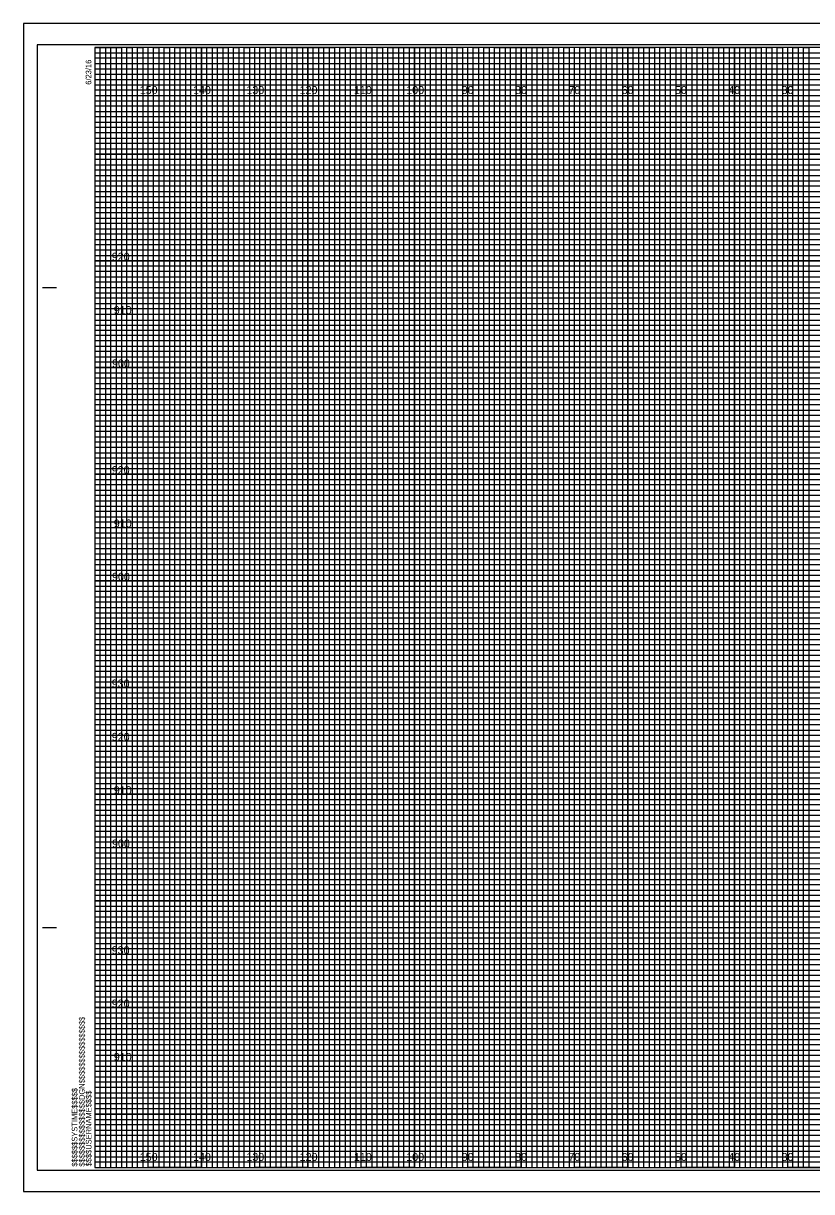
# Model space of a CAD drawing. Extents: x -13 to 323, y -4 to 214.
# Drawn here: x -13.4 to 134.5, y -4.5 to 214.5 of the extents above; entities that cross this region are included whole.
import ezdxf

# ---------------------------------------------------------------- set-up
doc = ezdxf.new("R2010")
doc.units = 0
for name, color, linetype in [('Prop XS Elevation Labels', 7, 'Continuous'), ('Prop XS Offset Labels', 7, 'Continuous'), ('Sheet Cross Section CELL', 7, 'Continuous'), ('Sheet Cross Section Grid Major CELL', 7, 'Continuous'), ('Sheet Cross Section Grid Middle CELL', 7, 'Continuous'), ('Sheet Cross Section Grid Minor 1 CELL', 7, 'Continuous'), ('Sheet Cross Section Grid Minor 2 CELL', 7, 'Continuous'), ('Sheet Cutting Line CELL', 7, 'Continuous'), ('Sheet DOT Grid CELL', 7, 'Continuous'), ('Sheet Plot Border Inside CELL', 7, 'Continuous'), ('Sheet Plot Border Outside CELL', 7, 'Continuous')]:
    doc.layers.add(name, color=color, linetype=linetype)

msp = doc.modelspace()

# ---------------------------------------------------------------- linework, layer by layer
at = {"layer": 'Sheet Cross Section CELL'}
for p, q in [((-9.8, 165), (-7.3, 165)), ((-9.7, 165), (-7.2, 165)), ((-9.8, 45), (-7.3, 45)), ((-9.7, 45), (-7.2, 45)), ((0, 0), (0, 0)), ((0, 0), (0, 0)), ((0, 0), (0, 0)), ((0, 0), (0, 0)), ((0, 0), (0, 0)), ((0, 0), (0, 0)), ((0, 0), (0, 0))]:
    msp.add_line(p, q, dxfattribs=at)
msp.add_lwpolyline([(320, 210), (0, 210), (0, 0), (320, 0)], close=True, dxfattribs=at)
at = {"layer": 'Sheet Cross Section Grid Major CELL'}
for p, q in [((10, 210), (0, 210)), ((10, 0), (10, 210)), ((30, 210), (20, 210)), ((20, 210), (20, 0)), ((30, 0), (30, 210)), ((50, 210), (40, 210)), ((40, 210), (40, 0)), ((50, 0), (50, 210)), ((70, 210), (60, 210)), ((60, 210), (60, 0)), ((70, 0), (70, 210)), ((90, 210), (80, 210)), ((80, 210), (80, 0)), ((90, 0), (90, 210)), ((110, 210), (100, 210)), ((100, 210), (100, 0)), ((110, 0), (110, 210)), ((130, 210), (120, 210)), ((120, 210), (120, 0)), ((130, 0), (130, 210)), ((20, 0), (10, 0)), ((40, 0), (30, 0)), ((60, 0), (50, 0)), ((80, 0), (70, 0)), ((100, 0), (90, 0)), ((120, 0), (110, 0)), ((140, 0), (130, 0))]:
    msp.add_line(p, q, dxfattribs=at)
for points in [[(0, 200), (320, 200), (320, 190), (0, 190)], [(0, 180), (320, 180), (320, 170), (0, 170)], [(0, 160), (320, 160), (320, 150), (0, 150)], [(0, 140), (320, 140), (320, 130), (0, 130)], [(0, 120), (320, 120), (320, 110), (0, 110)], [(0, 100), (320, 100), (320, 90), (0, 90)], [(0, 80), (320, 80), (320, 70), (0, 70)], [(0, 60), (320, 60), (320, 50), (0, 50)], [(0, 40), (320, 40), (320, 30), (0, 30)], [(0, 20), (320, 20), (320, 10), (0, 10)]]:
    msp.add_lwpolyline(points, dxfattribs=at)
at = {"layer": 'Sheet Cross Section Grid Middle CELL'}
for points in [[(0, 210), (5, 210), (5, 0), (15, 0), (15, 210), (25, 210), (25, 0), (35, 0), (35, 210), (45, 210), (45, 0), (55, 0), (55, 210), (65, 210), (65, 0), (75, 0), (75, 210), (85, 210), (85, 0), (95, 0), (95, 210), (105, 210), (105, 0), (115, 0), (115, 210), (125, 210), (125, 0), (135, 0)], [(0, 205), (275, 205)], [(0, 185), (320, 185), (320, 195), (0, 195)], [(0, 165), (320, 165), (320, 175), (0, 175)], [(0, 145), (320, 145), (320, 155), (0, 155)], [(0, 125), (320, 125), (320, 135), (0, 135)], [(0, 105), (320, 105), (320, 115), (0, 115)], [(0, 85), (320, 85), (320, 95), (0, 95)], [(0, 65), (320, 65), (320, 75), (0, 75)], [(0, 45), (320, 45), (320, 55), (0, 55)], [(0, 25), (320, 25), (320, 35), (0, 35)], [(0, 5), (320, 5), (320, 15), (0, 15)]]:
    msp.add_lwpolyline(points, dxfattribs=at)
at = {"layer": 'Sheet Cross Section Grid Minor 1 CELL'}
for p, q in [((0, 209), (260, 209)), ((260, 207.98), (0, 207.98)), ((0, 207.98), (0, 207)), ((0, 207), (260, 207)), ((260, 205.89), (0, 205.89)), ((0, 205.89), (0, 204)), ((0, 204), (320, 204))]:
    msp.add_line(p, q, dxfattribs=at)
for points in [[(0, 203), (270, 203), (320, 203), (320, 202), (0, 202)], [(0, 201), (320, 201), (320, 199), (0, 199)], [(0, 198), (320, 198), (320, 197), (0, 196.98)], [(0, 196), (320, 196), (320, 194), (0, 194)], [(0, 193), (320, 193), (320, 192), (0, 192)], [(0, 191), (320, 191), (320, 189), (0, 189)], [(0, 188), (320, 188), (320, 187), (0, 187)], [(0, 186), (320, 186), (320, 184), (0, 184)], [(0, 183), (320, 183), (320, 182), (0, 182)], [(0, 181), (320, 181), (320, 179), (0, 179)], [(0, 178), (320, 178), (320, 177), (0, 177)], [(0, 176), (320, 176), (320, 173.95), (320, 173), (320, 172), (0, 172)], [(0, 174), (320, 174), (320, 173), (0, 173)], [(0, 171), (320, 171), (320, 169), (0, 169.03)], [(0, 169.03), (320, 169), (320, 168), (0, 168)], [(0, 167), (320, 167), (320, 166), (0, 166)], [(0, 164), (320, 164), (320, 163), (0, 163)], [(0, 162), (320, 162), (320, 161), (0, 161)], [(-0.07, 158.89), (320, 158.89), (320, 157.88), (-0.07, 157.88)], [(0, 157), (320, 157), (320, 156), (0, 156)], [(0, 154), (320, 154), (320, 153), (0, 153)], [(0, 152), (320, 152), (320, 151), (0, 151)], [(0, 149), (320, 149), (320, 148), (0, 148)], [(0, 147), (320, 147), (320, 146), (0, 146)], [(0, 144), (320, 144), (320, 143), (0, 143)], [(0, 142), (320, 142), (320, 141), (0, 141)], [(0, 139), (320, 139), (319.99, 137.98), (0, 138)], [(0, 137), (320, 137), (320, 136), (0, 136)], [(0, 134), (320, 134), (320, 133), (0, 133)], [(0, 132), (320, 132), (320, 131), (0, 131)], [(0, 129), (320, 129), (320, 128), (0, 128)], [(0, 127), (320, 127), (320, 126), (0, 126)], [(0, 124), (320, 124), (320, 123), (0, 123)], [(0, 122), (320, 122), (320, 121), (0, 121)], [(0, 119), (320, 119), (320, 118), (0, 118)], [(0, 116.99), (320.07, 116.91), (320, 116), (0, 116)], [(0, 114), (320, 114), (320, 113), (0, 113)], [(0, 112), (320, 112), (320, 111), (0, 111)], [(0, 109), (320, 109), (320, 108), (0, 108)], [(0, 107), (320, 107), (320, 106), (0, 106)], [(0, 104), (320, 104), (320, 103), (0, 103)], [(0, 102), (320, 102), (320, 101), (0, 101)], [(0, 99), (320, 99), (320, 98), (0, 98)], [(0, 97), (320, 97), (320, 96), (0, 96)], [(0, 94), (320, 94), (320, 93), (0, 93)], [(0, 92), (320, 92), (320, 91), (0, 91)], [(0, 89), (320, 89), (320, 88), (0, 88)], [(0, 87), (320, 87), (320, 86), (0, 86)], [(0, 84), (320, 84), (320, 83), (0, 83)], [(0, 82), (320, 82), (320, 81), (0, 81)], [(0, 79), (320, 79), (319.99, 77.98), (0, 78)], [(0, 77), (320, 77), (320, 76), (0, 76)], [(0, 74), (320, 74), (320, 73), (0, 73)], [(0, 72), (320, 72), (320, 71), (0, 71)], [(0, 69), (320, 69), (320, 68), (0, 68)], [(0, 67), (320, 67), (320, 66), (0, 66)], [(0, 64), (320, 64), (320, 63), (0, 63)], [(0, 62), (320, 62), (320, 61), (0, 61)], [(0, 59), (320, 59), (320, 58), (0, 58)], [(0, 56.99), (320.07, 56.91), (320, 56), (0, 56)], [(0, 54), (320, 54), (320, 53), (0, 53)], [(0, 52), (320, 52), (320, 51), (0, 51)], [(0, 49), (320, 49), (320, 48), (0, 48)], [(0, 47), (320, 47), (320, 46), (0, 46)], [(0, 44), (320, 44), (320, 43), (0, 43)], [(0, 42), (320, 42), (320, 41), (0, 41)], [(0, 39), (320, 39), (320, 38), (0, 38)], [(0, 37), (320, 37), (320, 36), (0, 36)], [(0, 34), (320, 34), (320, 33), (0, 33)], [(0, 32), (320, 32), (320, 31), (0, 31)], [(0, 29), (320, 29), (320, 28), (0, 28)], [(0, 27), (320, 27), (320, 26), (0, 26)], [(0, 24), (320, 24), (320, 23), (0, 23)], [(0, 22), (320, 22), (320, 21), (0, 21)], [(0, 19), (320, 19), (320, 18), (0, 18)], [(0, 17), (320, 17), (320, 16), (0, 16)], [(0, 14), (320, 14), (320, 13), (0, 13)], [(0, 12), (320, 12), (320, 11), (0, 11)], [(0, 9), (320, 9), (320, 8), (0, 8)], [(0, 7), (320, 7), (320, 6), (0, 6)], [(0, 4), (320, 4), (320, 3), (0, 3)], [(0, 2), (320, 2), (320, 1), (0, 1)]]:
    msp.add_lwpolyline(points, dxfattribs=at)
at = {"layer": 'Sheet Cross Section Grid Minor 2 CELL'}
for points in [[(0, 0), (1, 0), (1, 210), (2, 210), (2, 0)], [(2, 0), (3, 0), (3, 210), (4, 210), (4, 0)], [(5, 0), (6, 0), (6, 210), (7, 210), (7, 0)], [(7, 0), (8, 0), (8, 210), (9, 210), (9, 0)], [(10, 0), (11, 0), (11, 210), (12, 210), (12, 0)], [(12, 0), (13, 0), (13, 210), (14, 210), (14, 0)], [(15, 0), (16, 0), (16, 210), (17, 210), (17, 0)], [(17, 0), (18, 0), (18, 210), (19, 210), (19, 0)], [(20, 0), (21, 0), (21, 210), (22, 210), (22, 0)], [(22, 0), (23, 0), (23, 210), (24, 210), (24, 0)], [(25, 0), (26, 0), (26, 210), (27, 210), (27, 0)], [(27, 0), (28, 0), (28, 210), (29, 210), (29, 0)], [(30, 0), (31, 0), (31, 210), (32, 210), (32, 0)], [(32, 0), (33, 0), (33, 210), (34, 210), (34, 0)], [(35, 0), (36, 0), (36, 210), (37, 210), (37, 0)], [(37, 0), (38, 0), (38, 210), (39, 210), (39, 0)], [(40, 0), (41, 0), (41, 210), (42, 210), (42, 0)], [(42, 0), (43, 0), (43, 210), (44, 210), (44, 0)], [(45, 0), (46, 0), (46, 210), (47, 210), (47, 0)], [(47, 0), (48, 0), (48, 210), (49, 210), (49, 0)], [(50, 0), (51, 0), (51, 210), (52, 210), (52, 0)], [(52, 0), (53, 0), (53, 210), (54, 210), (54, 0)], [(55, 0), (56, 0), (56, 210), (57, 210), (57, 0)], [(57, 0), (58, 0), (58, 210), (59, 210), (59, 0)], [(60, 0), (61, 0), (61, 210), (62, 210), (62, 0)], [(62, 0), (63, 0), (63, 210), (64, 210), (64, 0)], [(65, 0), (66, 0), (66, 210), (67, 210), (67, 0)], [(67, 0), (68, 0), (68, 210), (69, 210), (69, 0)], [(70, 0), (71, 0), (71, 210), (72, 210), (72, 0)], [(72, 0), (73, 0), (73, 210), (74, 210), (74, 0)], [(75, 0), (76, 0), (76, 210), (77, 210), (77, 0)], [(77, 0), (78, 0), (78, 210), (79, 210), (79, 0)], [(80, 0), (81, 0), (81, 210), (82, 210), (82, 0)], [(82, 0), (83, 0), (83, 210), (84, 210), (84, 0)], [(85, 0), (86, 0), (86, 210), (87, 210), (87, 0)], [(87, 0), (88, 0), (88, 210), (89, 210), (89, 0)], [(90, 0), (91, 0), (91, 210), (92, 210), (92, 0)], [(92, 0), (93, 0), (93, 210), (94, 210), (94, 0)], [(95, 0), (96, 0), (96, 210), (97, 210), (97, 0)], [(97, 0), (98, 0), (98, 210), (99, 210), (99, 0)], [(100, 0), (101, 0), (101, 210), (102, 210), (102, 0)], [(102, 0), (103, 0), (103, 210), (104, 210), (104, 0)], [(105, 0), (106, 0), (106, 210), (107, 210), (107, 0)], [(107, 0), (108, 0), (108, 210), (109, 210), (109, 0)], [(110, 0), (111, 0), (111, 210), (112, 210), (112, 0)], [(112, 0), (113, 0), (113, 210), (114, 210), (114, 0)], [(115, 0), (116, 0), (116, 210), (117, 210), (117, 0)], [(117, 0), (118, 0), (118, 210), (119, 210), (119, 0)], [(120, 0), (121, 0), (121, 210), (122, 210), (122, 0)], [(122, 0), (123, 0), (123, 210), (124, 210), (124, 0)], [(125, 0), (126, 0), (126, 210), (127, 210), (127, 0)], [(127, 0), (128, 0), (128, 210), (129, 210), (129, 0)], [(130, 0), (131, 0), (131, 210), (132, 210), (132, 0)], [(132, 0), (133, 0), (133, 210), (134, 210), (134, 0)]]:
    msp.add_lwpolyline(points, dxfattribs=at)
at = {"layer": 'Sheet Cutting Line CELL'}
for p, q in [((323.3, 214.5), (-13.4, 214.5)), ((-13.4, 214.5), (-13.4, -4.5)), ((-13.4, -4.5), (323.3, -4.5))]:
    msp.add_line(p, q, dxfattribs=at)
at = {"layer": 'Sheet DOT Grid CELL'}
for p, q in [((10, 0), (10, 210)), ((20, 0), (20, 210)), ((30, 0), (30, 210)), ((40, 0), (40, 210)), ((50, 0), (50, 210)), ((60, 0), (60, 210)), ((70, 0), (70, 210)), ((80, 0), (80, 210)), ((90, 0), (90, 210)), ((100, 0), (100, 210)), ((110, 0), (110, 210)), ((120, 0), (120, 210)), ((130, 0), (130, 210)), ((0, 200), (320, 200)), ((0, 190), (320, 190)), ((0, 180), (320, 180)), ((0, 170), (320, 170)), ((0, 160), (320, 160)), ((0, 150), (320, 150)), ((0, 140), (320, 140)), ((0, 130), (320, 130)), ((0, 120), (320, 120)), ((0, 110), (320, 110)), ((0, 100), (320, 100)), ((0, 90), (320, 90)), ((0, 80), (320, 80)), ((0, 70), (320, 70)), ((0, 60), (320, 60)), ((0, 50), (320, 50)), ((0, 40), (320, 40)), ((0, 30), (320, 30)), ((0, 20), (320, 20)), ((0, 10), (320, 10))]:
    msp.add_line(p, q, dxfattribs=at)
at = {"layer": 'Sheet Plot Border Inside CELL'}
msp.add_lwpolyline([(-10.8, -0.5), (322.4, -0.5), (322.4, 210.5), (-10.8, 210.5)], close=True, dxfattribs=at)
at = {"layer": 'Sheet Plot Border Outside CELL'}
msp.add_lwpolyline([(-13.4, -4.5), (323.3, -4.5), (323.3, 214.5), (-13.4, 214.5)], close=True, dxfattribs=at)

# ---------------------------------------------------------------- texts
at = {"layer": 'Prop XS Elevation Labels'}
for s, p in [('920', (3.19, 170)), ('910', (3.57, 160)), ('900', (3.24, 150)), ('920', (3.19, 130)), ('910', (3.57, 120)), ('900', (3.24, 110)), ('930', (3.18, 90)), ('920', (3.19, 80)), ('910', (3.57, 70)), ('900', (3.24, 60)), ('930', (3.18, 40)), ('920', (3.19, 30)), ('910', (3.57, 20))]:
    msp.add_text(s, height=1.5, dxfattribs=at).set_placement(p)
at = {"layer": 'Prop XS Offset Labels'}
for s, p in [('150', (8.44, 201.25)), ('140', (18.44, 201.25)), ('130', (28.44, 201.25)), ('120', (38.44, 201.25)), ('110', (48.62, 201.25)), ('100', (58.44, 201.25)), ('90', (68.86, 201.25)), ('80', (78.86, 201.25)), ('70', (88.86, 201.25)), ('60', (98.86, 201.25)), ('50', (108.86, 201.25)), ('40', (118.86, 201.25)), ('30', (128.86, 201.25)), ('150', (8.44, 1.25)), ('140', (18.44, 1.25)), ('130', (28.44, 1.25)), ('120', (38.44, 1.25)), ('110', (48.62, 1.25)), ('100', (58.44, 1.25)), ('90', (68.86, 1.25)), ('80', (78.86, 1.25)), ('70', (88.86, 1.25)), ('60', (98.86, 1.25)), ('50', (108.86, 1.25)), ('40', (118.86, 1.25)), ('30', (128.86, 1.25))]:
    msp.add_text(s, height=1.5, dxfattribs=at).set_placement(p)
at = {"layer": 'Sheet Cross Section CELL'}
for s, p in [('6/23/16', (-0.65, 203)), ('$$$$$$$$$$$$$$$$DGN$$$$$$$$$$$$$$$$', (-1.88, 0.18)), ('$$$$$$SYSTIME$$$$$', (-3.26, 0.18)), ('$$$$USERNAME$$$$', (-0.62, 0.23))]:
    msp.add_text(s, height=1.05, rotation=90, dxfattribs=at).set_placement(p)

doc.saveas('drawing.dxf')
